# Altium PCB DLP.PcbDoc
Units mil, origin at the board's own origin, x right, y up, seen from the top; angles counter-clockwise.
Board outline 6000 x 4000 mil, 2 copper layers (Top Layer, Bottom Layer); 62 components, 221 nets, 465 pads, 249 vias.
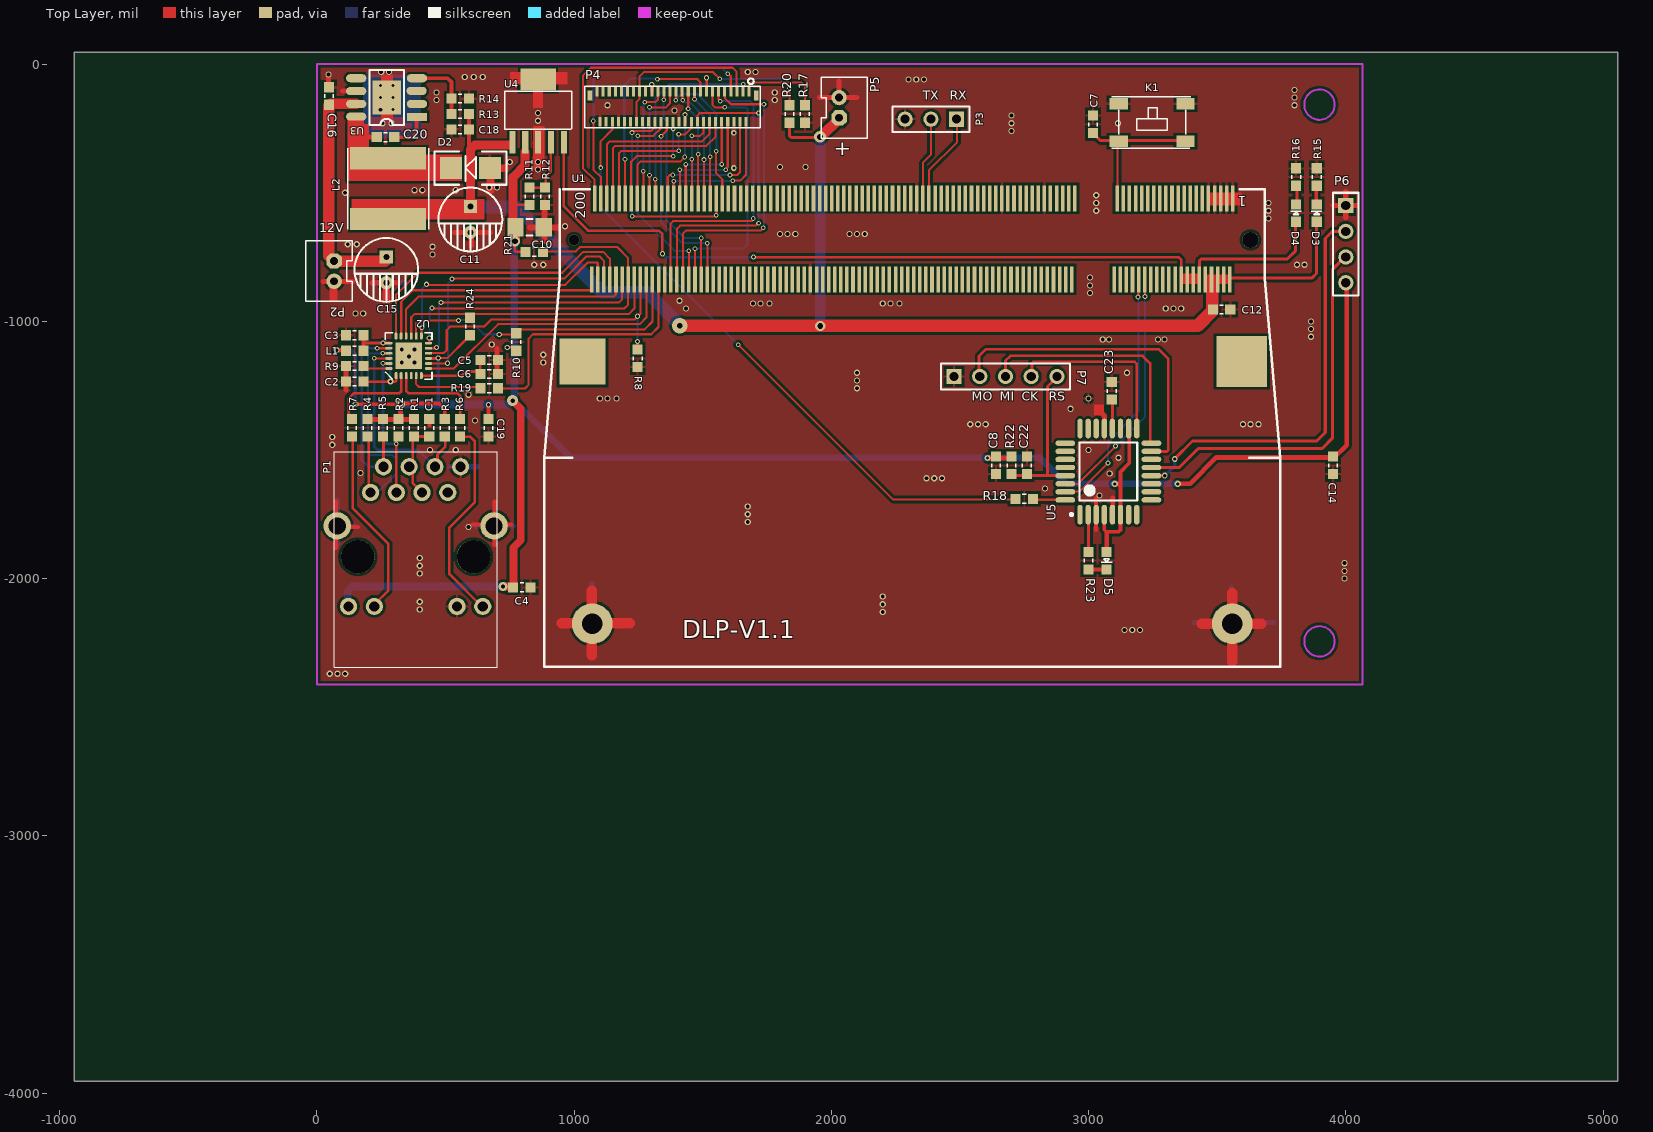
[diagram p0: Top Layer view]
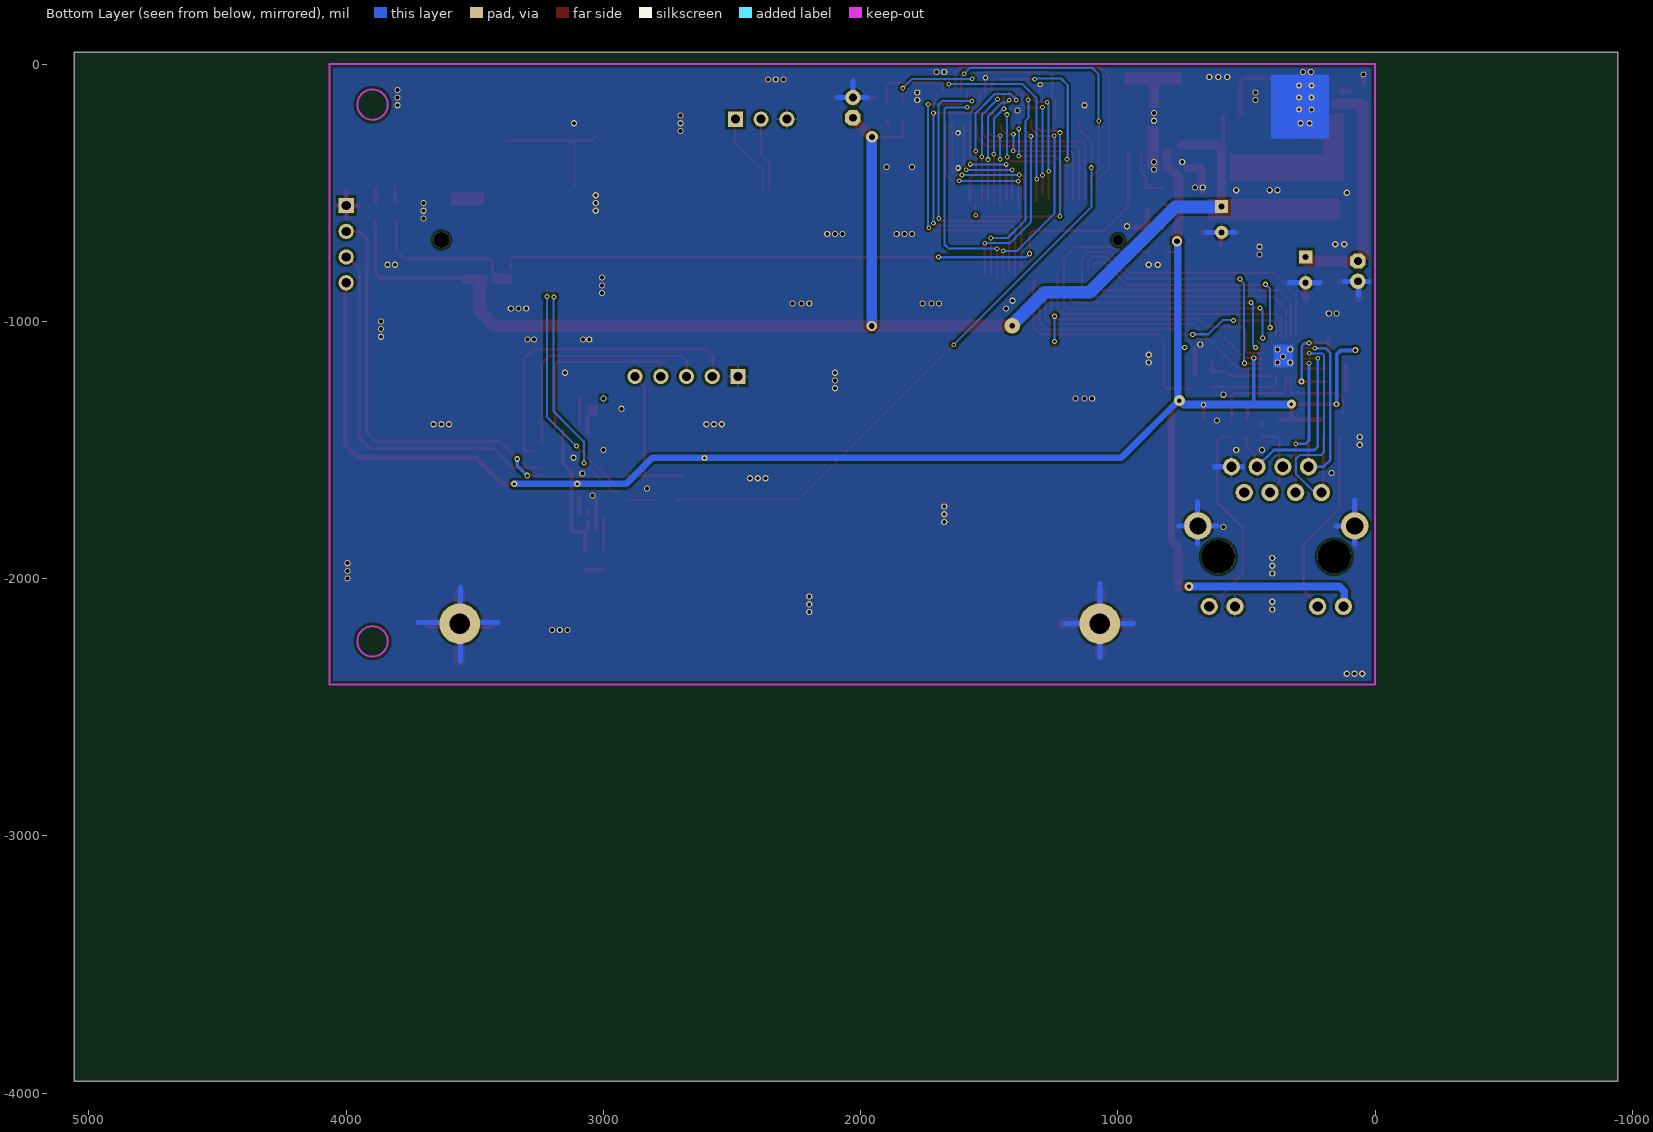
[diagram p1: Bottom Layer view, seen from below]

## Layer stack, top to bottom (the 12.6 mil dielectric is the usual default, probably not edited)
Top Layer: signal copper 1.4
Dielectric: dielectric 12.6, FR-4, Dk 4.8
Bottom Layer: signal copper 1.4

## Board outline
-943,-3954 5057,-3954 5057,46 -943,46

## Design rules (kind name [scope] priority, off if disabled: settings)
Clearance [All] p1: gap=6
ComponentClearance [All] p1 off: gap=10 collisioncheckmode=3 verticalgap=10
HoleSize [All] p1: absolutevalues=TRUE maxlimit=150 minlimit=1 maxpercent=80.000 minpercent=20.000
PolygonConnect [All] p1: connectstyle=Relief reliefconductorwidth=10 reliefentries=4 polygonreliefangle="90 Angle"
RoutingVias [All] p1: holewidth=14 width=28 viastyle="Through Hole" minholewidth=8 minwidth=15 maxholewidth=130 maxwidth=150
SolderMaskExpansion [All] p1: expansion=4
TestPointUsage [All] p1: valid=0 allowmultiple=FALSE
Testpoint [All] p1: side=15 testpointundercomponent=TRUE minsize=40 maxsize=100 preferedsize=60 minholesize=0 maxholesize=40 preferedholesize=32 testpointgrid=1 style=1023 order=0123456789
Width [All] p1: maxlimit=100 minlimit=8 preferedwidth=10 minimp=50.000000 maximp=50.000000 favimp=50.000000
17 further rules are at their usual default settings.

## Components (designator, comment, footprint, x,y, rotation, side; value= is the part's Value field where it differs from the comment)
C1 "104" 0603 437,-1414 r90 top
C2 "104" 0603 147,-1234 r180 top
C3 "104" 0603 147,-1054 r180 top
C4 "104" 0603 797,-2034 r180 top
C5 "104" 0603 670,-1150 r0 top
C6 "105" 0603 670,-1205 r0 top
C7 "100PF" 0603 3017,-234 r270 top
C8 "104" 0603 2640,-1560 r90 top
C10 "470uF/16V" 3216[1206] 827,-634 r0 top
C11 "470uF/16V" C6.3*12 597,-654 r90 top
C12 "100nF" 0603 3517,-954 r180 top
C14 "100nF" 0603 3950,-1560 r90 top
C15 "100uF/35V" C6.3*12 270,-850 r90 top
C16 "100nF" 0603 47,-124 r270 top
C18 "106" 0603 557,-254 r180 top
C19 "104" 0603 667,-1414 r90 top
C20 "10nF" 0603 267,-284 r0 top
C22 "Cap" 0603 2760,-1560 r90 top
C23 "Cap" 0603 3090,-1270 r90 top
D2 "SS34" SMA 597,-404 r180 top
D3 "BLUE" 0603-LED 3887,-579 r90 top
D4 "BLUE" 0603-LED 3807,-579 r90 top
D5 "BLUE" 0603-LED 3070,-1930 r270 top
K1 "AJ" 4*4*1.5 3117,-154 r0 top
L1 "120 OHM@100MHz" 0603 147,-1114 r180 top
L2 "10uH/4A" 8040 277,-484 r270 top
P1 "HR911105A" HR911105A 357,-1794 r0 top
P2 "CON2" PH2.0-2P 67,-844 r270 top
P3 "" HDR1X3 2487,-214 r180 top
P4 "FPC-51PIN" FH26-51S-0.3SHW 1680,-110 r0 top
P5 "Header 2" PH2.0-2P 2030,-130 r90 top
P6 "CSB" HDR1X4 4000,-550 r270 top
P7 "Header 5" HDR1X5 2477,-1214 r0 top
R1 "10R" 0603 377,-1414 r90 top
R2 "49R9" 0603 317,-1414 r90 top
R3 "49R9" 0603 497,-1414 r90 top
R4 "49R9" 0603 197,-1414 r90 top
R5 "49R9" 0603 257,-1414 r90 top
R6 "1K" 0603 557,-1414 r90 top
R7 "1K" 0603 137,-1414 r90 top
R8 "10K" 0603 1247,-1144 r90 top
R9 "12.1K" 0603 147,-1174 r0 top
R10 "10K" 0603 775,-1080 r270 top
R11 "52.3K" 0603 827,-514 r270 top
R12 "30.1K" 0603 887,-514 r270 top
R13 "4.3KF" 0603 557,-194 r0 top
R14 "1.5KF" 0603 557,-134 r0 top
R15 "1K" 0603 3887,-439 r270 top
R16 "1K" 0603 3807,-439 r270 top
R17 "Res1" 0603 1897,-194 r90 top
R18 "Res1" 0603 2750,-1690 r0 top
R19 "0R" 0603 670,-1260 r0 top
R20 "Res1" 0603 1837,-194 r90 top
R21 "1.5K" 0603 845,-730 r180 top
R22 "Res1" 0603 2700,-1560 r90 top
R23 "1K" 0603 3000,-1930 r270 top
R24 "10K" 0603 595,-1020 r90 top
U1 "MAX6-200" "SO-DIMM 200" 2317,-1414 r180 top locked
U2 "LAN8720A" QFN24_4X4MM 357,-1134 r90 top
U3 "LM22676" SO-8HP 277,-154 r180 top
U4 "TPS737" SOT223-6 860,-60 r0 top
U5 "ATmega48PA" 32A_M 3077,-1584 r90 top

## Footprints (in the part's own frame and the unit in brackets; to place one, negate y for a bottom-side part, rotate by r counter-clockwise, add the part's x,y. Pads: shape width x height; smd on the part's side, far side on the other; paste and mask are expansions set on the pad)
4*4*1.5 [mm]
  rect 1.8x1.1 smd: 1(0,0) 2(6.6,0) 3(0,-3.7) 4(6.6,-3.7)
  silkscreen extent -0.7,-4.4 7.1,0.7
32A_M [mm] "32-Pin Thin Quad Flat Pack 0.8 mm Pitch, IPC Low Density"
  oval 1.95x0.533 smd: 1(-4.25,2.8) 2(-4.25,2) 3(-4.25,1.2) 4(-4.25,0.4) 5(-4.25,-0.4) 6(-4.25,-1.2) 7(-4.25,-2) 8(-4.25,-2.8) 17(4.25,-2.8) 18(4.25,-2) 19(4.25,-1.2) 20(4.25,-0.4) 21(4.25,0.4) 22(4.25,1.2) 23(4.25,2) 24(4.25,2.8)
  oval 0.533x1.95 smd: 9(-2.8,-4.25) 10(-2,-4.25) 11(-1.2,-4.25) 12(-0.4,-4.25) 13(0.4,-4.25) 14(1.2,-4.25) 15(2,-4.25) 16(2.8,-4.25) 25(2.8,4.25) 26(2,4.25) 27(1.2,4.25) 28(0.4,4.25) 29(-0.4,4.25) 30(-1.2,4.25) 31(-2,4.25) 32(-2.8,4.25)
  silkscreen extent -4.37,-2.85 2.85,3.77, body extent -3.5,-3.5 3.5,3.5, height 1.2
0603 [mm]
  rect 1x1 smd: 1(-0.864,0) 2(0.864,0)
  silkscreen extent -0.18,-0.43 0.18,0.43
0603-LED [mm]
  rect 1x1 smd: 1(-0.864,0) 2(0.864,0)
  silkscreen extent -0.18,-0.51 0.18,0.56
3216[1206] [mm] "Chip Resistor; Body 3.2 x 1.6 mm (LxW typ)"
  rect 1.6x1.8 smd: 1(-1.4,0) 2(1.4,0)
  silkscreen extent -0.3,-0.8 0.3,0.8
8040 [mm]
  rect 2.2x7.5 smd: 1(-3,0) 2(3,0)
  silkscreen extent -4,-4 4,4
C6.3*12 [mm]
  rect 1.3x1.3 hole 0.6: 1(2.54,0)
  round 1.3 hole 0.6: 2(0,0)
  silkscreen extent -1.88,-3.15 4.42,3.15
FH26-51S-0.3SHW [mm]
  rect 0.45x1 smd: 0(-15.7,-0.3) 0(0.7,-0.3)
  rect 0.3x0.95 smd: 1(0,0.05) 2(-0.3,-2.91) 3(-0.6,0.05) 4(-0.9,-2.91) 5(-1.2,0.05) 6(-1.5,-2.91) 7(-1.8,0.05) 8(-2.1,-2.91) 9(-2.4,0.05) 10(-2.7,-2.91) 11(-3,0.05) 12(-3.3,-2.91) 13(-3.6,0.05) 14(-3.9,-2.91) 15(-4.2,0.05) 16(-4.5,-2.91) 17(-4.8,0.05) 18(-5.1,-2.91) 19(-5.4,0.05) 20(-5.7,-2.91) 21(-6,0.05) 22(-6.3,-2.91) 23(-6.6,0.05) 24(-6.9,-2.91) 25(-7.2,0.05) 26(-7.5,-2.91) 27(-7.8,0.05) 28(-8.1,-2.91) 29(-8.4,0.05) 30(-8.7,-2.91) 31(-9,0.05) 32(-9.3,-2.91) 33(-9.6,0.05) 34(-9.9,-2.91) 35(-10.2,0.05) 36(-10.5,-2.91) 37(-10.8,0.05) 38(-11.1,-2.91) 39(-11.4,0.05) 40(-11.7,-2.91) 41(-12,0.05) 42(-12.3,-2.91) 43(-12.6,0.05) 44(-12.9,-2.91) 45(-13.2,0.05) 46(-13.5,-2.91) 47(-13.8,0.05) 48(-14.1,-2.91) 49(-14.4,0.05) 50(-14.7,-2.91) 51(-15,0.05)
  silkscreen extent -16.2,-3.5 1.1,1.38
HDR1X3 [mm] "Connector; Header; 3 Position"
  rect 1.5x1.5 hole 0.9: 1(0,0)
  round 1.5 hole 0.9: 2(2.54,0) 3(5.08,0)
  silkscreen extent -1.27,-1.27 6.35,1.27
HDR1X4 [mm] "Connector; Header; 4 Position"
  rect 1.5x1.5 hole 0.9: 1(0,0)
  round 1.5 hole 0.9: 2(2.54,0) 3(5.08,0) 4(7.62,0)
  silkscreen extent -1.27,-1.27 8.89,1.27
HDR1X5 [mm] "Connector; Header; 5 Position"
  rect 1.5x1.5 hole 0.9: 1(0,0)
  round 1.5 hole 0.9: 2(2.54,0) 3(5.08,0) 4(7.62,0) 5(10.16,0)
  silkscreen extent -1.27,-1.27 11.43,1.27
HR911105A [mm]
  round 1.699 hole 1.001: 1(-3.762,3.275) 2(-2.492,5.815) 3(-1.222,3.275) 4(0.048,5.815) 5(1.318,3.275) 6(2.588,5.815) 7(3.858,3.275) 8(5.128,5.815) 9(-5.937,-7.975) 10(-3.397,-7.975) 11(4.773,-7.975) 12(7.313,-7.975)
  round 2.7 hole 1.7: 13(-7.057,-0.025) 14(8.433,-0.025)
  round 3.3 hole 3.3: ""(-5.027,-3.075) ""(6.403,-3.075)
  silkscreen extent -7.36,-14 8.74,7.3
PH2.0-2P [mil]
  oct 60x60 hole 30: 1(-78.74,0)
  round 60 hole 30: 2(0,0)
  silkscreen extent -157,-110 79,70
QFN24_4X4MM [mil]
  oval 28x11 smd: 1(-77.01,49.21) 2(-77.01,29.53) 3(-77.01,9.84) 4(-77.01,-9.84) 5(-77.01,-29.53) 6(-77.01,-49.21) 13(77.01,-49.21) 14(77.01,-29.53) 15(77.01,-9.84) 16(77.01,9.84) 17(77.01,29.53) 18(77.01,49.21)
  oval 11x28 smd: 7(-49.21,-77.01) 8(-29.53,-77.01) 9(-9.84,-77.01) 10(9.84,-77.01) 11(29.53,-77.01) 12(49.21,-77.01) 19(49.21,77.01) 20(29.53,77.01) 21(9.84,77.01) 22(-9.84,77.01) 23(-29.53,77.01) 24(-49.21,77.01)
  rect 103x103 smd: 25(0,0)
  silkscreen extent -91,-91 91,91
SMA [mm] "Molded Diode, 2-Leads, Body 4.3x2.7mm, IPC Medium Density"
  rect 2.15x2.15 smd: 1(-1.93,0) 2(1.93,0)
  silkscreen extent -3.56,-1.65 3.56,1.65, body extent -2.28,-1.42 2.29,1.42, height 2.95
SO-8HP [mm]
  rect 2x0.8 smd: 1(-2.847,1.29)
  oval 2x0.8 smd: 2(-2.847,0.02) 3(-2.813,-1.275) 4(-2.847,-2.52) 5(3.153,-2.52) 6(3.153,-1.25) 7(3.153,0.02) 8(3.153,1.265)
  rect 2.8x3.4 smd: 9(0.128,-0.615)
  silkscreen extent -1.55,-3.31 1.85,2.09
"SO-DIMM 200" [mm]
  round 1.6 hole 1.6: 0(-33.337,-18.553)
  rect 5x5 smd: 0(-32.487,-6.553)
  rect 4.572x4.572 smd: 0(32.613,-6.553)
  round 1.1 hole 1.1: 0(33.463,-18.553)
  rect 0.35x2.55 smd: 1(-31.587,-22.653) 2(-31.287,-14.653) 3(-30.987,-22.653) 4(-30.687,-14.653) 5(-30.387,-22.653) 6(-30.087,-14.653) 7(-29.787,-22.653) 8(-29.487,-14.653) 9(-29.187,-22.653) 10(-28.887,-14.653) 11(-28.587,-22.653) 12(-28.287,-14.653) 13(-27.987,-22.653) 14(-27.687,-14.653) 15(-27.387,-22.653) 16(-27.087,-14.653) 17(-26.787,-22.653) 18(-26.487,-14.653) 19(-26.187,-22.653) 20(-25.887,-14.653) 21(-25.587,-22.653) 22(-25.287,-14.653) 23(-24.987,-22.653) 24(-24.687,-14.653) 25(-24.387,-22.653) 26(-24.087,-14.653) 27(-23.787,-22.653) 28(-23.487,-14.653) 29(-23.187,-22.653) 30(-22.887,-14.653) 31(-22.587,-22.653) 32(-22.287,-14.653) 33(-21.987,-22.653) 34(-21.687,-14.653) 35(-21.387,-22.653) 36(-21.087,-14.653) 37(-20.787,-22.653) 38(-20.487,-14.653) 39(-20.187,-22.653) 40(-19.887,-14.653) 41(-15.987,-22.653) 42(-15.687,-14.653) 43(-15.387,-22.653) 44(-15.087,-14.653) 45(-14.787,-22.653) 46(-14.487,-14.653) 47(-14.187,-22.653) 48(-13.887,-14.653) 49(-13.587,-22.653) 50(-13.287,-14.653) 51(-12.987,-22.653) 52(-12.687,-14.653) 53(-12.387,-22.653) 54(-12.087,-14.653) 55(-11.787,-22.653) 56(-11.487,-14.653) 57(-11.187,-22.653) 58(-10.887,-14.653) 59(-10.587,-22.653) 60(-10.287,-14.653) 61(-9.987,-22.653) 62(-9.687,-14.653) 63(-9.387,-22.653) 64(-9.087,-14.653) 65(-8.787,-22.653) 66(-8.487,-14.653) 67(-8.187,-22.653) 68(-7.887,-14.653) 69(-7.587,-22.653) 70(-7.287,-14.653) 71(-6.987,-22.653) 72(-6.687,-14.653) 73(-6.387,-22.653) 74(-6.087,-14.653) 75(-5.787,-22.653) 76(-5.487,-14.653) 77(-5.187,-22.653) 78(-4.887,-14.653) 79(-4.587,-22.653) 80(-4.287,-14.653) 81(-3.987,-22.653) 82(-3.687,-14.653) 83(-3.387,-22.653) 84(-3.087,-14.653) 85(-2.787,-22.653) 86(-2.487,-14.653) 87(-2.187,-22.653) 88(-1.887,-14.653) 89(-1.587,-22.653) 90(-1.287,-14.653) 91(-0.987,-22.653) 92(-0.687,-14.653) 93(-0.387,-22.653) 94(-0.087,-14.653) 95(0.213,-22.653) 96(0.513,-14.653) 97(0.813,-22.653) 98(1.113,-14.653) 99(1.413,-22.653) 100(1.713,-14.653) 101(2.013,-22.653) 102(2.313,-14.653) 103(2.613,-22.653) 104(2.913,-14.653) 105(3.213,-22.653) 106(3.513,-14.653) 107(3.813,-22.653) 108(4.113,-14.653) 109(4.413,-22.653) 110(4.713,-14.653) 111(5.013,-22.653) 112(5.313,-14.653) 113(5.613,-22.653) 114(5.913,-14.653) 115(6.213,-22.653) 116(6.513,-14.653) 117(6.813,-22.653) 118(7.113,-14.653) 119(7.413,-22.653) 120(7.713,-14.653) 121(8.013,-22.653) 122(8.313,-14.653) 123(8.613,-22.653) 124(8.913,-14.653) 125(9.213,-22.653) 126(9.513,-14.653) 127(9.813,-22.653) 128(10.113,-14.653) 129(10.413,-22.653) 130(10.713,-14.653) 131(11.013,-22.653) 132(11.313,-14.653) 133(11.613,-22.653) 134(11.913,-14.653) 135(12.213,-22.653) 136(12.513,-14.653) 137(12.813,-22.653) 138(13.113,-14.653) 139(13.413,-22.653) 140(13.713,-14.653) 141(14.013,-22.653) 142(14.313,-14.653) 143(14.613,-22.653) 144(14.913,-14.653) 145(15.213,-22.653) 146(15.513,-14.653) 147(15.813,-22.653) 148(16.113,-14.653) 149(16.413,-22.653) 150(16.713,-14.653) 151(17.013,-22.653) 152(17.313,-14.653) 153(17.613,-22.653) 154(17.913,-14.653) 155(18.213,-22.653) 156(18.513,-14.653) 157(18.813,-22.653) 158(19.113,-14.653) 159(19.413,-22.653) 160(19.713,-14.653) 161(20.013,-22.653) 162(20.313,-14.653) 163(20.613,-22.653) 164(20.913,-14.653) 165(21.213,-22.653) 166(21.513,-14.653) 167(21.813,-22.653) 168(22.113,-14.653) 169(22.413,-22.653) 170(22.713,-14.653) 171(23.013,-22.653) 172(23.313,-14.653) 173(23.613,-22.653) 174(23.913,-14.653) 175(24.213,-22.653) 176(24.513,-14.653) 177(24.813,-22.653) 178(25.113,-14.653) 179(25.413,-22.653) 180(25.713,-14.653) 181(26.013,-22.653) 182(26.313,-14.653) 183(26.613,-22.653) 184(26.913,-14.653) 185(27.213,-22.653) 186(27.513,-14.653) 187(27.813,-22.653) 188(28.113,-14.653) 189(28.413,-22.653) 190(28.713,-14.653) 191(29.013,-22.653) 192(29.313,-14.653) 193(29.613,-22.653) 194(29.913,-14.653) 195(30.213,-22.653) 196(30.513,-14.653) 197(30.813,-22.653) 198(31.113,-14.653) 199(31.413,-22.653) 200(31.713,-14.653)
  round 4 hole 2: 201(-31.53,19.336) 202(31.657,19.336)
  silkscreen extent -36.29,-23.55 36.41,23.57
SOT223-6 [mm]
  rect 0.6x2.2 smd: 1(-2.54,-6.2) 2(-1.27,-6.2) 3(0,-6.2) 4(1.27,-6.2) 5(2.54,-6.2)
  rect 3.5x2.2 smd: 6(0,0)
  silkscreen extent -3.3,-4.9 3.3,-1.17

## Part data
C8: library part CAP
C22 C23: "Capacitor"
D5: library part LED2, "Typical RED, GREEN, YELLOW, AMBER GaAs LED"
P5: "Header, 2-Pin"
P6: library part "Header 4", "Header, 4-Pin"
P7: "Header, 5-Pin"
R17 R18 R20 R22: "Resistor"
R19 R21 R24: library part RES
R23: library part Res1, "Resistor"
U5: library part ATmega8-16AC, "8-Bit AVR Microcontroller with 8K Bytes of In-System Programmable Flash Memory"

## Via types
v1: diameter 24, hole 15, Top Layer to Bottom Layer, 142 vias
v2: diameter 18, hole 10, Top Layer to Bottom Layer, 61 vias
v3: diameter 20, hole 12, Top Layer to Bottom Layer, 23 vias
v4: diameter 23.62, hole 11.81, Top Layer to Bottom Layer, 5 vias
v5: diameter 22, hole 12, Top Layer to Bottom Layer, 5 vias
v6: diameter 23, hole 13, Top Layer to Bottom Layer, 2 vias
v7: diameter 40, hole 22, Top Layer to Bottom Layer, 2 vias
v8: diameter 35, hole 15, Top Layer to Bottom Layer, 2 vias
v9: diameter 25, hole 13, Top Layer to Bottom Layer, 2 vias
v10: diameter 42, hole 18, Top Layer to Bottom Layer, 1 vias
v11: diameter 23.62, hole 14, Top Layer to Bottom Layer, 1 vias
v12: diameter 60, hole 22, Top Layer to Bottom Layer, 1 vias
v13: diameter 45, hole 22, Top Layer to Bottom Layer, 1 vias
v14: diameter 22, hole 13, Top Layer to Bottom Layer, 1 vias

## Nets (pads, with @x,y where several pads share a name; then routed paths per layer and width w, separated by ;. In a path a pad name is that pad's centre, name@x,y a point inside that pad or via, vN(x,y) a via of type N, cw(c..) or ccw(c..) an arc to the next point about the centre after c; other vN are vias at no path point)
3P3V: D4.1 U1.12 U1.14 U1.16 U1.18 U4.5 | length 3322.4
  Top Layer w10: U4.5@960,-343 960,-553 1054,-647 1329,-647 1343,-661 v3@1343,-736 ; v3@1696,-750 3350,-750 3360,-760 U1.18@3360,-795
  Top Layer w12: U1.12@3431,-807 3431,-765 3439,-757 3773,-757 3805,-725 D4.1@3805,-610
  Bottom Layer w10: v3@1344,-738 1356,-750 v3(1698,-750)
  other v3: 1343,-737
5VIN: C11.1 C12.2 C18.1 D3.1 L2.2 P5.1 R13.2 R20.1 U1.2 U1.4 U1.6 U1.8 U1.10 U4.1 | length 5263.4
  Top Layer w12: R20.1@1833,-228 R20.1@1833.1,-228.62 ; R20.1@1837,-231 1837,-278 1844,-285 v13@1955,-285 ; 3538,-831 3869,-831 3886,-814 D3.1@3886,-610
  Top Layer w15: 592,-321 R13.2@592,-201
  Top Layer w35: C11.1@597,-553 597,-332 614,-315 U4.1@752,-315
  Top Layer w40: v13@1956,-284 1957,-284 1957,-285 P5.1@2034,-208
  Top Layer w50: v12(1411,-1017) 3424,-1017 3481,-960 U1.8@3481,-870
  Bottom Layer w40: v7(1957,-1018) v13@1957,-285
  Bottom Layer w50: C11.1@598,-555 777,-555 1109,-887 1284,-887 v12@1412.5,-1015.5
  other v13: 1956,-283
+12: C15.1 C16.2 P2.1 U3.7 | length 922.3
  Top Layer w40: C16.2@54,-154 U3.7@152.05,-154
  Top Layer w45: C16.2@47,-161 47,-745 69,-767 264,-767 C15.1@274,-757
AUD3_RXD: U1.114
AUD3_TXC: U1.110
AUD3_TXD: U1.112
AUD3_TXFS: U1.116
CAN1_RX: U1.119
CAN1_TX: U1.117
CAN2_RX: U1.124
CAN2_TX: U1.122
CLK1_N: U1.84
CLK1_P: U1.82
CPUSYNC: P4.1 R17.2 | length 313.9
  Top Layer w8: P4.1@1680,-104 1680,-80 1689,-71 1882,-71 1897,-86 R17.2@1897,-149
CSB_CS: P6.3 U5.13 | length 1466.4
  Top Layer w12: U5.13@3262,-1568 3353,-1568 3427,-1494 3908,-1494 3949,-1453 3949,-797 3996,-750 P6.3
  Top Layer w15: U5.13@3239,-1569 U5.13@3244.33,-1568.92
CSB_SIG: P6.2 U5.12 | length 1607.4
  Top Layer w12: U5.12@3249,-1600 v6@3295,-1600 ; v5@3335,-1540 3335,-1534 3404,-1465 3887,-1465 3920,-1432 3920,-678 3948,-650 P6.2
  Top Layer w15: U5.12@3243,-1598 U5.12@3244.39,-1598.05
  Bottom Layer w12: v6(3296,-1600) 3335,-1561 v5(3335,-1535)
CSI0_DAT12: U1.107
CSI0_DAT13: U1.105
CSI0_DAT14: U1.99
CSI0_DAT15: U1.115
CSI0_DAT16: U1.97
CSI0_DAT17: U1.95
CSI0_DAT18: U1.103
CSI0_DAT19: U1.101
CSI0_DATA_EN/VOL-: U1.24
CSI0_HSYNCH: U1.113
CSI0_PIXCLK: U1.111
CSI0_VSYNCH: U1.109
CSI_CLK0M: U1.85
CSI_CLK0P: U1.87
CSI_D0M: U1.81
CSI_D0P: U1.83
CSI_D1M: U1.77
CSI_D1P: U1.79
CSPI1_CLK: U1.47
CSPI1_CS0: U1.41
CSPI1_MISO: U1.43
CSPI1_MOSI: U1.45
CSPI1_RDY: U1.49
CSPI2_CLK: U1.31
CSPI2_CS0: U1.25
CSPI2_CS1: U1.33
CSPI2_MISO: U1.35
CSPI2_MOSI: U1.29
CSPI2_RDY: U1.27
DISP0_CLK: P4.3 U1.179 | length 786.8
  Top Layer w8: U1.179@1316,-534 v2@1316,-446 ; P4.3@1656.38,-100 v2@1656.38,-79
  Bottom Layer w8: v2@1316,-447 1316,-133 1371,-78 v2(1657,-78)
  other v2: 1316,-448
DISP0_CONTRAST: U1.177
DISP0_DAT0: P4.7 U1.197 | length 1065
  Top Layer w8: v2@1075,-222 1075,-410 1105,-440 U1.197@1105,-485 ; v2@1599,-37 1609,-47 P4.7@1609,-98
  Bottom Layer w8: v2@1075,-222 1075,-40 1100,-15 1576,-15 v2(1598,-37)
  other v2: 1075,-221
DISP0_DAT1: P4.8 U1.171 | length 469.6
  Top Layer w8: U1.171 v2@1411,-412 ; v2@1589,-409 1597.32,-400.68 P4.8@1597.32,-232
  Bottom Layer w8: v2(1410,-411) v2(1589,-411)
DISP0_DAT2: P4.9 U1.170 | length 1142.9
  Top Layer w8: U1.170@1424,-800 1423,-799 1423,-659 1436,-646 1727,-646 v2@1737,-636 ; P4.9@1586,-97 1586,-132 1610,-156 v2(1738,-156)
  Bottom Layer w8: v2@1738,-637 v2(1738,-156)
  other v2: 1736,-636
DISP0_DAT3: P4.10 U1.169 | length 437
  Top Layer w8: U1.169@1434,-524 v2(1434,-390) ; v2(1574,-390) P4.10@1574,-225
  Bottom Layer w8: v2@1436,-390 v2(1574,-390)
DISP0_DAT4: P4.11 U1.174 | length 1125.7
  Top Layer w8: U1.174@1375,-804 1375,-621 1386,-610 1690,-610 v2@1699,-601 ; P4.11@1562,-116 1562,-138 v2@1567,-143
  Bottom Layer w8: v2@1563,-144 1684,-144 1697,-157 v2@1697,-599
  other v2: 1696,-600 1568,-144
DISP0_DAT5: P4.12 U1.193 | length 657.6
  Top Layer w8: U1.193@1151,-518 1151,-327 1160,-318 1514,-318 1550,-282 P4.12@1550,-233
DISP0_DAT6: P4.13 U1.166 | length 1051.2
  Top Layer w8: U1.166 v2(1470,-717) ; P4.13 1538.27,-159.27 1547,-168 v2(1586,-168)
  Bottom Layer w8: v2@1471,-717 1658,-717 1674,-701 1674,-174 1668,-168 v2(1586,-168) v2@1585,-167
DISP0_DAT7: P4.14 U1.195 | length 675.6
  Top Layer w8: U1.195@1128,-526 1128,-311 1139,-300 1498,-300 1527,-271 P4.14@1527,-226
DISP0_DAT8: P4.16 U1.167 | length 362.8
  Top Layer w8: v2@1457,-279 1490,-279 1502.84,-266.16 P4.16 ; U1.167@1458,-549 v2(1458,-370)
  Bottom Layer w8: v2(1458,-370) v2@1458,-279
  other v2: 1458,-278
DISP0_DAT9: P4.17 U1.189 | length 785.3
  Top Layer w8: U1.189@1198,-522.14 v2@1198,-371 ; v2@1324,-58 1479,-58 1490.78,-69.78 P4.17@1490.78,-102
  Bottom Layer w8: v2(1198,-370) 1195,-367 1195,-82 1221,-56 1321,-56 v2(1324,-59)
DISP0_DAT10: P4.18 U1.172 | length 1193
  Top Layer w8: U1.172@1400,-822 1400,-640 1412,-628 1706,-628 v2@1716,-618 ; P4.18@1479.21,-213 1479.21,-200 1489.21,-190 v2@1719,-190
  Bottom Layer w8: v2(1717,-618) v2@1717,-189
  other v2: 1717,-190
DISP0_DAT11: P4.19 U1.161 | length 450.1
  Top Layer w8: v2@1467.78,-137 P4.19@1467.78,-105 ; U1.161@1529,-531 v2@1529,-364
  Bottom Layer w8: v2@1468,-137 1529,-198 v2(1529,-360) v2@1531,-362
  other v2: 1468,-136
DISP0_DAT12: P4.20 U1.191 | length 558.3
  Top Layer w8: U1.191@1175,-532 1175,-346 1184,-337 v2(1407,-337) ; v2@1405,-273 1431.59,-273 1455.59,-249 P4.20@1455.59,-236
  Bottom Layer w8: v2@1406,-335 v2(1406,-272)
DISP0_DAT13: P4.21 U1.165 | length 442.6
  Top Layer w8: v2@1443.78,-175 P4.21@1443.78,-112 ; U1.165@1482,-541 v2(1482,-351)
  Bottom Layer w8: v2@1446.5,-176.5 1482,-212 1482,-350 v2@1481,-351
  other v2: 1443,-173
DISP0_DAT14: P4.22 U1.185 | length 534
  Top Layer w8: U1.185@1246,-533 1246,-391 1259,-378 1414,-378 v2@1430,-362 ; P4.22@1432,-228 v2@1432,-196
  Bottom Layer w8: v2@1431,-361 v2@1431,-197
  other v2: 1430,-361 1431,-196
DISP0_DAT15: P4.23 U1.163 | length 471.7
  Top Layer w8: v2@1420.78,-141 P4.23@1420.78,-109 ; U1.163@1505,-535 v2(1505,-371)
  Bottom Layer w8: v2@1423,-141 1423,-143 1430,-150 1451,-150 1505,-204 1505,-369 v2@1506,-370
  other v2: 1422,-141
DISP0_DAT16: P4.25 U1.157 | length 586.7
  Top Layer w8: v2@1396,-141 P4.25@1396,-105 ; v2(1552,-339) 1552,-424 1576,-448 U1.157@1576,-535
  Bottom Layer w8: v2@1396,-137 1417,-116 1478,-116 1553,-191 v2@1553,-339
  other v2: 1395,-140
DISP0_DAT17: P4.26 U1.187 | length 487.7
  Top Layer w8: U1.187@1222,-559 1222,-379 1243,-358 v2(1385,-358) ; v2@1385,-254 P4.26@1385,-222
  Bottom Layer w8: v2(1385,-358) v2@1385,-254
  other v2: 1385,-252
DISP0_DAT18: P4.27 U1.181 | length 466
  Top Layer w8: U1.181@1293,-504 v2@1293,-431 ; v2@1294,-169 1356,-169 1372.91,-152.09 P4.27
  Bottom Layer w8: v2(1293,-432) v2@1293,-169
  other v2: 1293,-168
DISP0_DAT19: P4.28 U1.162 | length 733.9
  Top Layer w8: v2@1335,-280 v2(1338,-280) 1361,-257 1361,-234.1 P4.28@1361.1,-234 ; P4.28@1361.01,-224.57 P4.28@1361,-223 ; U1.162@1518,-821 v2(1518,-696)
  Bottom Layer w8: v2@1336,-280 1337,-281 1337,-613 1420,-696 v2(1518,-696)
DISP0_DAT20: P4.29 U1.164 | length 796.8
  Top Layer w8: v2@1349,-139 1349.29,-139 P4.29@1349.29,-112 ; U1.164@1494,-812 v2@1494,-677
  Bottom Layer w8: v2@1348,-140 1348,-210 1360,-222 1360,-607 1429,-676 v2(1494,-676)
  other v2: 1349,-138
DISP0_DAT21: P4.30 U1.168 | length 781.4
  Top Layer w8: v2@1244,-279 1308,-279 1338,-249 P4.30@1338,-233.1 ; P4.30@1337.93,-224.57 P4.30@1338,-221 ; U1.168@1446,-821 v2@1446,-727
  Bottom Layer w8: v2@1246,-277 1246,-580 1392,-726 v2@1444,-726
  other v2: 1445,-726 1247,-279
DISP0_DAT22: P4.31 U1.183 | length 450
  Top Layer w8: U1.183@1269,-525 v2@1269,-417 ; v2(1275,-148) 1316,-148 1326,-138 P4.31@1326,-122
  Bottom Layer w8: v2@1269,-417 1269,-156 v2@1276,-149
  other v2: 1269,-416
DISP0_DAT23: P4.32 U1.159 | length 826.9
  Top Layer w8: v2(1226,-592) 1553,-592 U1.159@1553,-520 ; v2@1226,-266 1232,-260 1300,-260 1314,-246 P4.32@1314,-241 ; P4.32@1313.02,-224.59 P4.32@1313,-224
  Bottom Layer w8: v2@1225,-592 v2(1225,-266)
  other v2: 1553,-588
DISP0_DRDY: P4.2 U1.173 | length 599.4
  Top Layer w8: U1.173@1387,-559 v2(1387,-455) ; v2(1617,-453) 1646,-453 1668,-431 P4.2@1668,-224.76
  Bottom Layer w8: v2@1388,-454 v2@1617,-454
DISP0_HSYNCH: P4.5 U1.199 | length 1142.5
  Top Layer w8: U1.199@1078,-525 U1.199@1078.11,-522.06 ; U1.199@1080,-485 1080,-450 1034,-404 1034,-45 1065,-14 1616,-14 1632,-30 P4.5@1632,-93
DISP0_VSYNCH: P4.4 U1.175 | length 576.5
  Top Layer w8: U1.175@1364,-531 1364,-439 1372,-431 v2@1386,-431 ; v2@1603,-431 1635,-431 1645,-421 P4.4@1645,-227
  Bottom Layer w8: v2@1388,-431 v2@1607,-431
  other v2: 1384,-431 1606,-431
DMD: P4.41
EIM_BCLK/VOL+: U1.22
EIM_D20: U1.23
ENET0_100MLED2: R7.2 U2.2 | length 344
  Top Layer w10: R7.2@124,-1367 124,-1299 144,-1279 321,-1279 327.47,-1272.53 U2.2
ENET0_LINKLED1: R6.2 U2.3 | length 367.2
  Top Layer w10: U2.3 347.16,-1270.16 356.16,-1279.16 546.16,-1279.16 557,-1290 R6.2
ENET_CRS_DV: U1.190 U2.11 | length 965.4
  Top Layer w8: U2.11@439,-1104.47 v3@466.47,-1104.47 ; v3@485,-926 1175,-926 1187,-914 U1.190@1187,-874 ; U1.190@1186,-833 U1.190@1186.04,-837.11
  Bottom Layer w8: v3@464,-1104 475,-1093 475,-935 483,-927 v3@485,-927
  other v3: 465,-1102 483,-926
ENET_MDC: U1.198 U2.13 | length 935.4
  Top Layer w8: v3@406,-1022 v3@406.21,-1022.21 ; U2.13@407,-1053.79 v3@407,-1022 ; v3@424,-858 966,-858 1053,-771 1089,-771 1092,-774 U1.198@1092,-795
  Bottom Layer w8: v3@406,-1024 408,-1022 408,-874 v3@426.5,-855.5
  other v3: 408,-1024 426,-856
ENET_MDIO: R21.1 U1.188 U2.12 | length 1449.9
  Top Layer w8: U2.12@437,-1084.79 v3(437,-1064) ; v3@450,-950 1195,-950 1210,-935 1210,-754 1167,-711 1024,-711 1007,-728 R21.1@877,-728
  Bottom Layer w8: v3(437,-1064) 437,-958 445.5,-949.5 v3@451.5,-949.5
  other v3: 447,-948
ENET_NINT: R10.1 U1.180 U2.14 | length 1126.6
  Top Layer w8: U2.14@386.21,-1056 386.21,-1005.79 396,-996 v3@551,-996 ; v3@707,-1051 755,-1051 ; R10.1@770,-1031 1274,-1031 1304.66,-1000.34 U1.180@1304.66,-869 ; U1.180@1304.01,-837.11 U1.180@1304,-836
  Bottom Layer w8: v3@552,-995 593,-995 648,-1050 v3@709,-1050
  other v3: 709,-1051 550,-996
ENET_NRST: R24.2 U1.186 U2.15 | length 1095.5
  Top Layer w8: U2.15@366,-1063 367,-1062 367,-984 379,-972 1212,-972 1234,-950 U1.186@1234,-815
ENET_REF_CLK: R19.2 U1.178 | length 1010.6
  Top Layer w8: R19.2@704,-1261 809,-1261 823,-1247 823,-1067 840,-1050 1300,-1050 1328.28,-1021.72 1328.28,-893 U1.178@1327,-840
ENET_RX_ER: R8.2 U1.184 U2.10 | length 1162.9
  Top Layer w8: U2.10@438,-1125 440,-1123 494,-1123 505,-1112 505,-1034 519,-1020 651,-1020 679,-992 1236,-992 1258,-970 U1.184@1258,-871 ; R8.2@1246,-1110 v3(1246,-1078)
  Bottom Layer w8: v3@1247,-1082 v3@1247,-980
  other v3: 1246,-980
ENET_RXD0: U1.196 U2.8 | length 1068
  Top Layer w8: U2.8@441,-1163 v3@507,-1163 ; v3@525,-834 961,-834 1047,-748 1099,-748 1115.68,-764.68 U1.196@1115.68,-801
  Bottom Layer w8: v3@507,-1163 509,-1161 509,-854 v3@525,-838
  other v3: 508,-1163 526,-835
ENET_RXD1: U1.182 U2.7 | length 1037
  Top Layer w8: U2.7@435,-1183 533,-1183 705,-1011 1255,-1011 1281,-985 U1.182@1281,-876
ENET_TX_EN: U1.192 U2.16 | length 969.6
  Top Layer w8: U2.16@346,-1064 347,-1063 347,-952 395,-904 1154,-904 1162,-896 U1.192@1162,-877
ENET_TXD0: U1.200 U2.17 | length 892.6
  Top Layer w8: U2.17@328,-1059 328,-924 373,-879 U1.200@1067,-879
ENET_TXD1: U1.194 U2.18 | length 1194.5
  Top Layer w8: U2.18@308,-1056 308,-896 393,-811 954,-811 1035,-730 1113,-730 1139,-756 U1.194@1139,-880
ETH_RXN0: P1.6 R3.1 U2.22 | length 813.8
  Top Layer w8: v2(223,-1143.84) U2.22
  Top Layer w10: P1.6@469,-1583 469,-1518 499,-1488 R3.1@499,-1450
  Bottom Layer w10: v2(223,-1143.84) 223,-1487 236,-1500 393.8,-1500 P1.6
ETH_RXP0: P1.3 R2.1 U2.23 | length 586.8
  Top Layer w8: v2(257,-1163.53) U2.23
  Top Layer w10: P1.3@309,-1665 R2.1@309,-1458
  Bottom Layer w10: v2(257,-1163.53) 257,-1463 270,-1476 v2(309,-1476)
ETH_TXN0: P1.2 R5.1 U2.20 | length 742.8
  Top Layer w8: v2(234,-1104.47) U2.20
  Top Layer w10: P1.2@259,-1565 R5.1@259,-1447
  Bottom Layer w10: v2(234,-1104.47) 193.53,-1104.47 174,-1124 174,-1539 200.08,-1565.08 P1.2
ETH_TXP0: P1.1 R4.1 U2.21 | length 986.1
  Top Layer w8: v2(256,-1124.16) U2.21
  Top Layer w10: P1.1@202,-1673 R4.1@202,-1450
  Bottom Layer w8: P1.1@218,-1673 227,-1673 308,-1592 308,-1535 292,-1519 209,-1519 198,-1508 198,-1132 205.84,-1124.16 v2(256,-1124.16)
  Bottom Layer w10: v2(256,-1124.16) v2@256.16,-1124.16
FAN_ERR: P4.45
FEC_A3V2: C2.1 C3.1 L1.1 U2.1 U2.19 | length 471.4
  Top Layer w10: 181.01,-1084 U2.19@281,-1084 ; C2.1@192,-1234 304.79,-1234 307.79,-1231 U2.1
  Top Layer w15: L1.1 C3.1
  Bottom Layer w10: v2@254,-1085 273,-1085 286,-1098 v5@286,-1235
  other v2: 257,-1084
  other v5: 286,-1234
GEN_3V3: C4.2 C8.2 C10.1 C14.2 C19.2 D5.1 L1.2 P1.9 P6.4 R1.2 R2.2 R3.2 R4.2 R5.2 R10.2 R11.2 R21.2 R22.2 R24.1 U2.9 U4.2 U5.4 U5.6 U5.18 | length 9103.7
  Top Layer w8: v3@473,-1143 507,-1143 R24.1@585.5,-1064.5
  Top Layer w10: v3(740,-1101) R10.2@760,-1101 ; 756.1,-547 R11.2@829,-547 ; v7@770,-695 770,-726 774,-730 R21.2@803,-730 ; R21.2@810.67,-727.15 R21.2@812,-727
  Top Layer w12: U2.9@443,-1144 v3@470,-1144
  Top Layer w15: v6@75,-1112 L1.2@111,-1112 ; v14@155,-1322 v8@324,-1322 ; v8@325,-1320 476,-1320 497,-1341 R3.2 ; C19.2 v3@667,-1327 ; U5.4@3061,-1777.75 3061,-1810 3069,-1818 3117,-1818 3124,-1811 U5.6@3124,-1774 ; U5.4@3061.82,-1751.33 U5.4@3062,-1738 ; U5.6@3124,-1758 3124,-1585 3158,-1551 U5.18@3158,-1425
  Top Layer w18: v5(2607,-1531) R22.2@2696,-1531 ; D5.1@3070,-1893 3070,-1820 ; v9(3102,-1632) 3119,-1632 ; v9@3346,-1631 3395,-1631 3497,-1529 3956,-1529 4003,-1482 P6.4@4003,-843
  Top Layer w20: R4.2@204,-1381 R1.2@367,-1381 ; R2.2@325,-1370 v8@325,-1320
  Top Layer w30: v8(724,-2031) C4.2@757,-2031 ; v10@760,-1309 762,-1309 793,-1340 793,-1851 764,-1880 C4.2@764,-2033 ; C4.2@761,-2036 C4.2@761.16,-2033.86
  Top Layer w35: C10.1@763,-623 763,-439 810,-392 U4.2@810,-342
  Top Layer w40: v7@770,-683 C10.1@770,-639
  Bottom Layer w10: v3(740,-1101) 757,-1101
  Bottom Layer w12: 472,-1313 v3@472,-1141
  Bottom Layer w15: v6@78,-1113 135,-1113 149,-1127 v14@149,-1321
  Bottom Layer w25: v10@760,-1303 988,-1531 2811,-1531 2912,-1632 v9(3347,-1632)
  Bottom Layer w30: P1.9@120,-2108 120,-2049 138,-2031 v8(724,-2031) ; v8@328,-1323 744,-1323 767,-1300 v7@767,-687
  other v3: 667,-1324 472,-1143
  other v6: 77,-1112
  other v7: 770,-688
  other v8: 326,-1322
  other v10: 761,-1308
  other v14: 150,-1322
GND: C1.2 C2.2 C3.2 C4.1 C5.2 C6.2 C7.1 C8.1 C10.2 C11.2 C12.1 C14.1 C15.2 C16.1 C18.2 C19.1 C22.2 C23.2 D2.1 K1.1 K1.2 P1.8 P1.11 P1.13 P1.14 P2.2 P3.3 P4.6 P4.15 P4.24 P4.33 P4.44 P4.50 P4.51 P5.2 P6.1 P7.1 R8.1 R9.1 R12.2 R14.2 R15.1 R16.1 R17.1 U1.1 U1.3 U1.5 U1.7 U1.9 U1.51 U1.65 U1.93 U1.128 U1.149 U1.176 U1.201 U1.202 U2.25 U3.6 U3.9 U4.3 U4.6 U5.3 U5.5 U5.21 | length 5815.6
  Top Layer w10: P4.15@1514,-109 P4.15@1514.03,-108.02 ; P4.15@1514.97,-108.03 1514.99,-108.99 P4.15@1515,-110 ; P4.15@1515,-99 v3(1515,-53)
  Top Layer w12: P4.33 v3@1302.05,-84
  Top Layer w16: 75,-1880 75,-1700 ; P1.13@100,-1800 160,-1800 ; 605,-1790 755,-1790 ; 690,-1870 690,-1700 ; 3029,-1811 3029,-1687 ; U5.5@3094,-1753 3094,-1685
  Top Layer w20: 25,-845 140,-845 ; C16.1@45,-75 v1@45,-50 ; 100,-105 U3.6@135,-105 ; 113,-1267 113,-1194 ; R9.1@114.72,-1174.12 R9.1@115,-1170 ; 215,-850 305,-850 ; 535,-655 675,-655 ; 600,-705 C11.2@600,-660 ; C6.2@700,-1200 700,-1105 ; 1955,-130 2100,-130 ; P5.2@2030,-120 2030,-65 ; 3032,-1338 3062,-1368 U5.21@3062,-1430 ; 3950,-550 4040,-550 ; 4000,-595 4000,-495
  Top Layer w25: 830,-635 935,-635 ; 885,-685 R12.2@885,-565
  Top Layer w30: 65,-910 P2.2@65,-845 ; 270,-910 C15.2 ; v1@675,-490 D2.1@675,-400 ; D2.1@675,-405 730,-405
  Top Layer w40: 951,-2174 1216,-2174 ; 1069,-2298 1069,-2047 ; 3439,-2176 3672,-2176 ; 3558,-2321 3558,-2056
  Bottom Layer w20: 25,-845 120,-845 ; 65,-900 P2.2@65,-855 ; 80,-1865 80,-1695 ; P1.13@80,-1795 150,-1795 ; 215,-850 335,-850 ; 515,-1565 625,-1565 ; 545,-655 655,-655 ; 615,-1795 765,-1795 ; 690,-1865 690,-1700 ; 940,-2175 1205,-2175 ; 1070,-2305 1070,-2020 ; 1975,-130 2090,-130 ; P5.2@2030,-135 2030,-65 ; 3410,-2170 3720,-2170 ; 3555,-2320 3555,-2035
  other v1: 50,-2370 80,-2370 110,-2370 3140,-2200 3170,-2200 3200,-2200 2200,-2130 400,-2120 2200,-2100 400,-2090 2200,-2070 3995,-2000 400,-1980 3995,-1970 400,-1950 3995,-1940 400,-1920 590,-1800 1675,-1780 1675,-1750 1675,-1720 3043,-1677 2830,-1650 2370,-1610 2400,-1610 2430,-1610 3082,-1592 170,-1590 3116,-1530 440,-1500 540,-1500 3000,-1500 60,-1480 60,-1450 2540,-1400 2570,-1400 2600,-1400 3600,-1400 3630,-1400 3660,-1400 615,-1385 2930,-1340 1100,-1300 1130,-1300 1165,-1300 3000,-1300 590,-1285 2100,-1260 2100,-1230 2100,-1200 3150,-1200 330,-1160 380,-1160 880,-1160 358,-1137 880,-1130 330,-1110 380,-1110 680,-1090 3055,-1070 3080,-1070 3270,-1070 3295,-1070 3865,-1060 3865,-1030 3865,-1000 150,-970 180,-970 1435,-950 3300,-950 3330,-950 3360,-950 1695,-930 1725,-930 1760,-930 2200,-930 2230,-930 2265,-930 1410,-920 3005,-890 3005,-860 3005,-830 845,-780 880,-780 3810,-780 3840,-780 450,-740 450,-710 120,-700 155,-700 1800,-660 1830,-660 1860,-660 2070,-660 2100,-660 2130,-660 965,-630 3700,-600 3030,-570 3700,-570 3030,-540 3700,-540 3030,-510 110,-500 380,-490 410,-490 540,-490 670,-480 700,-480 860,-410 1800,-400 1900,-400 750,-380 860,-380 2700,-260 255,-230 290,-230 2700,-230 3115,-230 860,-220 2700,-200 860,-190 1390,-180 1130,-160 3800,-160 465,-140 1780,-140 3800,-130 465,-110 1780,-110 3800,-100 2300,-60 2330,-60 2360,-60 575,-50 610,-50 645,-50 45,-40 250,-30 280,-30 1675,-30 1705,-30
  other v3: 1302,-79
  other v4: 295.57,-177.05 247.34,-129.8 295.57,-129.8 247.34,-82.76 295.57,-82.56
  other v5: 1621,-404 1621,-267
  other v11: 247.34,-177.05
GPIO_0_CLKO: U1.126
"GPIO_4/SLEEP WAKE": U1.20
HDMI_CEC_IN: U1.90
HDMI_CLKM: U1.100
HDMI_CLKP: U1.98
HDMI_D0M: U1.104
HDMI_D0P: U1.102
HDMI_D1M: U1.96
HDMI_D1P: U1.94
HDMI_D2M: U1.88
HDMI_D2P: U1.86
HDMI_HPD: U1.92
I2C1_SCL: U1.106
I2C1_SDA: U1.108
I2C2_SCL: U1.158
I2C2_SDA: U1.160
I2C3_SCL: U1.118
I2C3_SDA: U1.120
KEY_COL2/SD3_CD_B: U1.21
LCD_CTL: P4.37 P4.38 R20.2 | length 858
  Top Layer w8: P4.38@1243,-219 1243,-147 1255,-135 1255,-47 1271,-31 1540,-31 v2(1566,-57) ; P4.38@1243.94,-224.53 P4.38@1244,-226 ; R20.2@1837.78,-156 v2@1837.78,-93
  Bottom Layer w8: v2@1565,-57 1800,-57 1835.5,-92.5 v2@1838.5,-92.5
  other v2: 1837,-93
LVDS0_CLK_N: U1.141
LVDS0_CLK_P: U1.143
LVDS0_TX0_N: U1.133
LVDS0_TX0_P: U1.135
LVDS0_TX1_N: U1.145
LVDS0_TX1_P: U1.147
LVDS0_TX2_N: U1.131
LVDS0_TX2_P: U1.129
LVDS0_TX3_N: U1.137
LVDS0_TX3_P: U1.139
LVDS1_CLK_N: U1.146
LVDS1_CLK_P: U1.148
LVDS1_TX0_N: U1.136
LVDS1_TX0_P: U1.134
LVDS1_TX1_N: U1.130
LVDS1_TX1_P: U1.132
LVDS1_TX2_N: U1.144
LVDS1_TX2_P: U1.142
LVDS1_TX3_N: U1.138
LVDS1_TX3_P: U1.140
MISO: P7.3 U5.16 | length 956.9
  Top Layer w10: P7.3@2677,-1219 2677,-1153 2696,-1134 3210,-1134 3239,-1163 U5.16@3239,-1472
MOSI: P7.2 U5.15 | length 1240.8
  Top Layer w10: P7.2@2574,-1218 2574,-1135 2600,-1109 3273,-1109 3309,-1145 3309,-1501 3304,-1506 U5.15@3270,-1506
MX6_ONOFF: U1.37
NANDF_ALE: U1.150
NANDF_CLE: U1.152
NANDF_CS0: U1.11
NANDF_CS1: U1.13
NANDF_CS2: U1.15
NANDF_CS3: U1.155
NANDF_WP_B: U1.154
NetC1_1: C1.1 P1.4 P1.5 R1.1 | length 285.7
  Top Layer w10: R1.1@372,-1457 372,-1629 P1.5@410,-1667
  Top Layer w12: R1.1 C1.1
NetC5_1: C5.1 C6.1 U2.6 | length 284.5
  Top Layer w10: U2.6 564.99,-1211.01 581,-1195 629,-1195 C6.1@634,-1190 ; C6.1@635,-1202 C5.1@635,-1154
NetC20_1: C20.1 D2.2 L2.1 U3.8 | length 140.7
  Top Layer w15: U3.8@151,-210 151,-263 172,-284 ; C20.1@232.97,-284.86 C20.1@237,-285
  Top Layer w19.68: 172,-284 C20.1@226,-284
NetC20_2: C20.2 U3.1 | length 146.8
  Top Layer w15: C20.2@303,-284 373,-284 387,-270 U3.1@387,-213
NetC23_1: C23.1 U5.20 | length 104
  Top Layer w12: U5.20@3093,-1404 C23.1@3093,-1300
NetD3_2: D3.2 R15.2 | length 60
  Top Layer w12: D3.2@3885,-541 R15.2@3885,-481
NetD4_2: D4.2 R16.2 | length 63
  Top Layer w10: D4.2 D4.2@3810,-545
  Top Layer w12: D4.2@3810,-535 R16.2@3810,-475
NetD5_2: D5.2 R23.2 | length 68
  Top Layer w15: R23.2@3001,-1964 D5.2@3069,-1964
NetP1_10: P1.10 R7.1 | length 742.5
  Top Layer w10: R7.1@139,-1448 139,-1450 139,-1726 278,-1865 278,-2046 225,-2099 P1.10@225,-2111
NetP1_12: P1.12 R6.1 | length 802.7
  Top Layer w8: P1.12@640.99,-2107.99 P1.12
  Top Layer w10: R6.1 596,-1448 613,-1465 613,-1704 515,-1802 515,-1982 P1.12@640.99,-2107.99
NetP4_46: P4.46 R18.1 | length 2430.1
  Top Layer w8: v2(1103,-402) 1103,-300 1149,-254 P4.46@1149,-230.5 ; v2(1638,-1091) 2239,-1692 2716,-1692 R18.1
  Bottom Layer w8: v2(1103,-402) 1103,-556 v2(1638,-1091)
NetR9_2: R9.2 U2.24 | length 89.8
  Top Layer w8: R9.2@190.21,-1183.21 U2.24
NetR11_1: R11.1 R12.1 U4.4 | length 221.2
  Top Layer w10: R11.1@825.1,-480 R12.1@898,-480 ; R12.1@890,-481 890,-438 910,-418 U4.4@910,-341
NetR13_1: R13.1 R14.1 U3.4 | length 254.3
  Top Layer w15: U3.4@386,-53 U3.4@389.13,-53.12 ; U3.4@403,-55 508,-55 523,-70 R13.1@523,-195
NetR19_1: R19.1 U2.5 | length 284.6
  Top Layer w8: U2.5@386,-1214 386,-1244 397,-1255 R19.1@635,-1255 ; U2.5@386.98,-1211.02 U2.5@387,-1210
NetR23_1: R23.1 U5.2 | length 123
  Top Layer w12: R23.1@2999,-1889 U5.2@2999,-1766
NRESET: C7.2 K1.3 K1.4 U1.39 | length 532.5
  Top Layer w8: U1.39@3112,-477 K1.3@3112,-303
  Top Layer w12: C7.2@3027,-279 3045,-297 K1.4@3378,-297
PCIE_RXM: U1.76
PCIE_RXP: U1.74
PCIE_TXM: U1.80
PCIE_TXP: U1.78
RST: C22.1 P7.5 R22.1 U5.29 | length 614.8
  Top Layer w12: R22.1@2694,-1599.75 U5.29 ; 2840,-1597 2840,-1253 2878,-1215 P7.5
SATA_RXN: U1.56
SATA_RXP: U1.54
SATA_TXN: U1.58
SATA_TXP: U1.60
SCK: P7.4 U5.17 | length 716.2
  Top Layer w10: P7.4@2780,-1215 2780,-1163 2786,-1157 3179,-1157 3188,-1166 U5.17@3188,-1416
SCL: P4.43
SD1_CLK: U1.156
SD1_DAT0/CSI0_PWN: U1.17
SD1_DAT1/TOUCH_NEINT1: U1.151
SD1_DAT2/RTC_GPIO: U1.153
SD2_CLK: U1.46
SD2_CMD: U1.50
SD2_DATA0: U1.44
SD2_DATA1: U1.52
SD2_DATA2: U1.42
SD2_DATA3: U1.48
SD3_CLK: U1.59
SD3_CMD: U1.57
SD3_DATA0: U1.63
SD3_DATA1: U1.61
SD3_DATA2: U1.55
SD3_DATA3: U1.53
SD3_RST/SD3_WP: U1.19
SDA: P4.42
STANDBY: R18.2 U5.32 | length 99.6
  Top Layer w8: U5.32@2909.68,-1694.01 U5.32@2912,-1694
  Top Layer w10: R18.2@2793.76,-1694.24 U5.32@2891,-1694.24
UART1_RX: P3.1 U1.89 | length 333.6
  Top Layer w8: U1.89@2379,-505 2379,-413 2489,-303 P3.1@2489,-217
UART1_TX: P3.2 U1.91 | length 284.1
  Top Layer w8: U1.91@2356,-528 U1.91@2355.99,-522.14 ; U1.91@2356,-488 2356,-383 2388,-351 P3.2@2388,-223
UART2_CTS: U1.26
UART2_RTS: U1.28
UART2_RXD: U1.32 U5.31 | length 903.5
  Top Layer w8: U5.31@2939,-1662 2964,-1662 3074,-1552 v3@3077,-1552 ; v3@3194.05,-905.05 U1.32@3194.05,-880
  Bottom Layer w8: v3@3076,-1550 3076,-1468 3194,-1350 v3@3194,-904
  other v3: 3075,-1551 3192,-905
UART2_TXD: U1.30 U5.30 | length 887.5
  Top Layer w8: U5.30@2938,-1632 2959,-1632 v3@3106,-1485 ; U1.30@3218.05,-878 3219,-878.95 v3@3219,-904
  Top Layer w12: U5.30@2908,-1631 U5.30@2909.68,-1631.01
  Bottom Layer w8: v3@3109,-1488 3109,-1482 3219,-1372 v3@3219,-903
  other v3: 3105,-1485 3220,-903
UART3_CTS: U1.34
UART3_RTS: U1.36
UART3_RXD: U1.40
UART3_TXD: U1.38
UART4_RXD: U1.123
UART4_TXD: U1.121
UART5_RXD: U1.125
UART5_TXD: U1.127
USB_H1_OC: U1.73
USB_H1_PWR_EN: U1.67
USB_H1_VBUS: U1.75
USB_HOST_DN: U1.69
USB_HOST_DP: U1.71
USB_OTG_DN: U1.66
USB_OTG_DP: U1.68
USB_OTG_ID: U1.72
USB_OTG_OC: U1.62
USB_OTG_PWR_EN: U1.64
USB_OTG_VBUS: U1.70
pads on no net: P1. P1.7 P4.0 P4.34 P4.35 P4.36 P4.39 P4.40 P4.47 P4.48 P4.49 U1.0 U2.4 U3.2 U3.3 U3.5 U5.1 U5.7 U5.8 U5.9 U5.10 U5.11 U5.14 U5.19 U5.22 U5.23 U5.24 U5.25 U5.26 U5.27 U5.28

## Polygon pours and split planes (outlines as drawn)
GND on Top Layer "Bottom Layer-No Net" (solid, remove dead copper, pour order 1000): -214,64 -205,73 4256,73 4256,-2345 4032,-2569 3987,-2614 -290,-2614
GND on Bottom Layer "Bottom Layer-No Net" (solid, remove dead copper, pour order 1001): -281,113 4359,113 4413,167 4211,-35 4211,-2685 -254,-2685 -348,-2591

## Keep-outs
Keep-Out Layer:
  circle w7.87: c3897.64,-157.48 r59.06
  circle w7.87: c3897.64,-2244.09 r59.06
  lines w8: 0,-2411 0,0 4065,0 4065,-2411 0,-2411

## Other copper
Top Layer:
  rectangle net GND: 430,-1410 445,-1390
  rectangle net GND: 3465,-550 3595,-500
  rectangle net GND: 250,-220 295,-40
  rectangle net GND: 840,-170 880,-80
  rectangle net GND: 750,-80 975,-30
  rectangle net GND: 840,-410 885,-240
  rectangle net GND: 3021,-1366 3060,-1323
  rectangle net NetC20_1: 120,-455 565,-351
  rectangle net 5VIN: 134,-604 651,-524
  rectangle net 5VIN: 3451,-854 3549,-817
  rectangle net 3P3V: 3357,-854 3432,-814
  rectangle net NetC20_1: 119,-452 203,-233
  rectangle net NetC20_1: 120,-269 184,-191
Bottom Layer:
  rectangle net GND: 320,-1180 395,-1090
  rectangle net GND: 180,-290 405,-40

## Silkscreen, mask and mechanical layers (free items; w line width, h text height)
Top Overlay:
  text "TX" at 2355,-150 h60
  text "RX" at 2460,-150 h60
  text "+" at 2010,-355 h60
  text "12V" at 10,-665 h60
  text "MO" at 2545,-1320 h60
  text "MI" at 2655,-1320 h60
  text "CK" at 2740,-1320 h60
  text "RS" at 2845,-1320 h60
  text "DLP-V1.1" at 1420,-2255 h120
